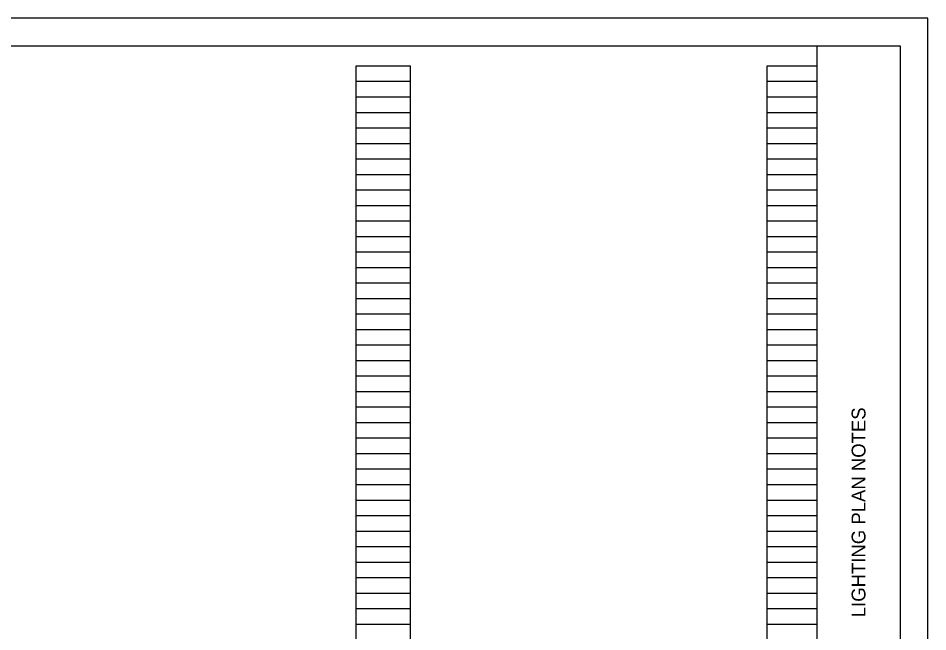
# Model space of a CAD drawing. Extents: x 0 to 34, y 0 to 22.
# Drawn here: x 17.58 to 34, y 10.92 to 22 of the extents above; entities that cross this region are included whole.
import ezdxf

# ---------------------------------------------------------------- set-up
doc = ezdxf.new("R2010")
doc.units = 0
for name, color, linetype in [('SH_Border', 7, 'Continuous'), ('SH_Cut_Line', 7, 'Continuous'), ('SH_Data', 7, 'Continuous')]:
    doc.layers.add(name, color=color, linetype=linetype)

msp = doc.modelspace()

# ---------------------------------------------------------------- linework, layer by layer
at = {"layer": 'SH_Border'}
msp.add_line((32, 0.5), (32, 21.5), dxfattribs=at)
msp.add_lwpolyline([(1.5, 21.5), (33.5, 21.5), (33.5, 0.5), (1.5, 0.5)], close=True, dxfattribs=at)
at = {"layer": 'SH_Cut_Line'}
msp.add_lwpolyline([(0, 0), (34, 0), (34, 22), (0, 22)], close=True, dxfattribs=at)
at = {"layer": 'SH_Data'}
for p, q in [((23.68, 0.98), (23.68, 21.14)), ((23.68, 21.14), (24.66, 21.14)), ((24.66, 0.98), (24.66, 21.14)), ((31.1, 0.98), (31.1, 21.14)), ((31.1, 21.14), (32, 21.14)), ((32, 0.98), (32, 21.14)), ((23.68, 20.86), (24.66, 20.86)), ((31.1, 20.86), (32, 20.86)), ((23.68, 20.58), (24.66, 20.58)), ((31.1, 20.58), (32, 20.58)), ((23.68, 20.3), (24.66, 20.3)), ((31.1, 20.3), (32, 20.3)), ((23.68, 20.02), (24.66, 20.02)), ((31.1, 20.02), (32, 20.02)), ((23.68, 19.74), (24.66, 19.74)), ((31.1, 19.74), (32, 19.74)), ((23.68, 19.46), (24.66, 19.46)), ((31.1, 19.46), (32, 19.46)), ((23.68, 19.18), (24.66, 19.18)), ((31.1, 19.18), (32, 19.18)), ((23.68, 18.9), (24.66, 18.9)), ((31.1, 18.9), (32, 18.9)), ((23.68, 18.62), (24.66, 18.62)), ((31.1, 18.62), (32, 18.62)), ((23.68, 18.34), (24.66, 18.34)), ((31.1, 18.34), (32, 18.34)), ((23.68, 18.06), (24.66, 18.06)), ((31.1, 18.06), (32, 18.06)), ((23.68, 17.78), (24.66, 17.78)), ((31.1, 17.78), (32, 17.78)), ((23.68, 17.5), (24.66, 17.5)), ((31.1, 17.5), (32, 17.5)), ((23.68, 17.22), (24.66, 17.22)), ((31.1, 17.22), (32, 17.22)), ((23.68, 16.94), (24.66, 16.94)), ((31.1, 16.94), (32, 16.94)), ((23.68, 16.66), (24.66, 16.66)), ((31.1, 16.66), (32, 16.66)), ((23.68, 16.38), (24.66, 16.38)), ((31.1, 16.38), (32, 16.38)), ((23.68, 16.1), (24.66, 16.1)), ((31.1, 16.1), (32, 16.1)), ((23.68, 15.82), (24.66, 15.82)), ((31.1, 15.82), (32, 15.82)), ((23.68, 15.54), (24.66, 15.54)), ((31.1, 15.54), (32, 15.54)), ((23.68, 15.26), (24.66, 15.26)), ((31.1, 15.26), (32, 15.26)), ((23.68, 14.98), (24.66, 14.98)), ((31.1, 14.98), (32, 14.98)), ((23.68, 14.7), (24.66, 14.7)), ((31.1, 14.7), (32, 14.7)), ((23.68, 14.42), (24.66, 14.42)), ((31.1, 14.42), (32, 14.42)), ((23.68, 14.14), (24.66, 14.14)), ((31.1, 14.14), (32, 14.14)), ((23.68, 13.86), (24.66, 13.86)), ((31.1, 13.86), (32, 13.86)), ((23.68, 13.58), (24.66, 13.58)), ((31.1, 13.58), (32, 13.58)), ((23.68, 13.3), (24.66, 13.3)), ((31.1, 13.3), (32, 13.3)), ((23.68, 13.02), (24.66, 13.02)), ((31.1, 13.02), (32, 13.02)), ((23.68, 12.74), (24.66, 12.74)), ((31.1, 12.74), (32, 12.74)), ((23.68, 12.46), (24.66, 12.46)), ((31.1, 12.46), (32, 12.46)), ((23.68, 12.18), (24.66, 12.18)), ((31.1, 12.18), (32, 12.18)), ((23.68, 11.9), (24.66, 11.9)), ((31.1, 11.9), (32, 11.9)), ((23.68, 11.62), (24.66, 11.62)), ((31.1, 11.62), (32, 11.62)), ((23.68, 11.34), (24.66, 11.34)), ((31.1, 11.34), (32, 11.34)), ((23.68, 11.06), (24.66, 11.06)), ((31.1, 11.06), (32, 11.06))]:
    msp.add_line(p, q, dxfattribs=at)

# ---------------------------------------------------------------- texts
msp.add_text('LIGHTING PLAN NOTES', height=0.25, rotation=90, dxfattribs=at).set_placement((32.875, 11.183))

doc.saveas('drawing.dxf')
